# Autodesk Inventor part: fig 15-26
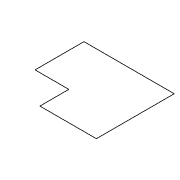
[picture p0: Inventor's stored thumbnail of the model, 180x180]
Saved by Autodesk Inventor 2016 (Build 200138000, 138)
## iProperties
Created: 2005-03
Part Number: fig 15-26
Document SubType Name: Sheet Metal
Designer: CADCIM
Manufacturer: Standard
Standards Organization: Custom
Density: 1 g/cm^3
Sheet Metal Rule: Default
Material: Generic
Appearance: Default
Author: CADCIM
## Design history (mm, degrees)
sketch "Sketch1"
  geometry: L1 (29.25, 32.25)-(-19.875, 32.25); L2 (-19.875, 32.25)-(-19.875, 5.625); L3 (-19.875, 5.625)-(-1.5, 5.625); L4 (-1.5, 5.625)-(-1.5, -10.125); L5 (-1.5, -10.125)-(29.25, -10.125); L6 (29.25, -10.125)-(29.25, 32.25)
  constraints: 12 end point, 4 parallel, 1 horizontal, 1 perpendicular
body "Solid1"
other parameters: "Thickness" = 0.5, "BendRadius" = 0.5 (= Thickness), "BendReliefWidth" = 0.5 (= Thickness), "BendReliefDepth" = 0.25 (= 0.5 x Thickness), "CornerReliefSize" = 2 (= 4 x Thickness), "SeamGap" = 0.01, "MinimumRemnant" = 1 (= 2 x Thickness), "TransitionRadius" = 0.5 (= BendRadius), "JacobiRadiusSize" = 0.5 (= Thickness), "GapSize" = 0.5 (= Thickness), "d0" = 0.5 (= BendRadius)
